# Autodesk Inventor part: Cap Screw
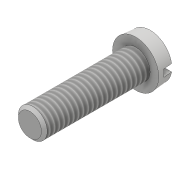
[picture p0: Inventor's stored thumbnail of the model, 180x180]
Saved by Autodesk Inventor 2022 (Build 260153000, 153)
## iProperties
Created: 2016-05
Part Number: Cap Screw
Material: Generic
Document SubType Name: Modeling
Designer: CADCIM
Density: 1 g/cm^3
Appearance: Default
Author: CADCIM
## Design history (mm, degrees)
sketch "Sketch2"
  geometry: C1 r 4.8 at (0, 0); 1 further point
  constraints: 1 centre point, 1 coincident
  dimensions: "d0" = 9.6 diameter of C1
extrude "Extrusion1" new body sketch "Sketch2" distance "d1" = 3; taper "d2" = -5 deg
sketch "Sketch3"
  geometry: C1 r 3 at (0, 0); 1 further point
  constraints: 1 centre point, 1 coincident
  dimensions: "d3" = 6 diameter of C1
extrude "Extrusion2" join sketch "Sketch3" distance "d4" = 22; taper "d5" = 0 deg
sketch "Sketch4"
  geometry: L1 (-13.358, -0.75)-(13.048, -0.75); L2 (13.048, -0.75)-(13.048, 0.75); L3 (13.048, 0.75)-(-13.358, 0.75); L4 (-13.358, 0.75)-(-13.358, -0.75); L5 (0, 0)-(-15.613, 0)
  constraints: 10 end point, 3 parallel, 1 horizontal, 1 perpendicular, 1 other
  dimensions: "d6" = 1.5 distance of L3.end L1.start
extrude "Extrusion3" cut sketch "Sketch4" distance "d7" = 1.8; taper "d8" = 0 deg
thread "Thread1" dims "d9" = 10, "d10" = 0
chamfer "Chamfer1" distance "d11" = 0.6; stored, may be unused: second distance "d12" = 2, angle "d13" = 45 deg
body "Solid1"
